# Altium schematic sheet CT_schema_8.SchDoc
size 287 x 160 mm
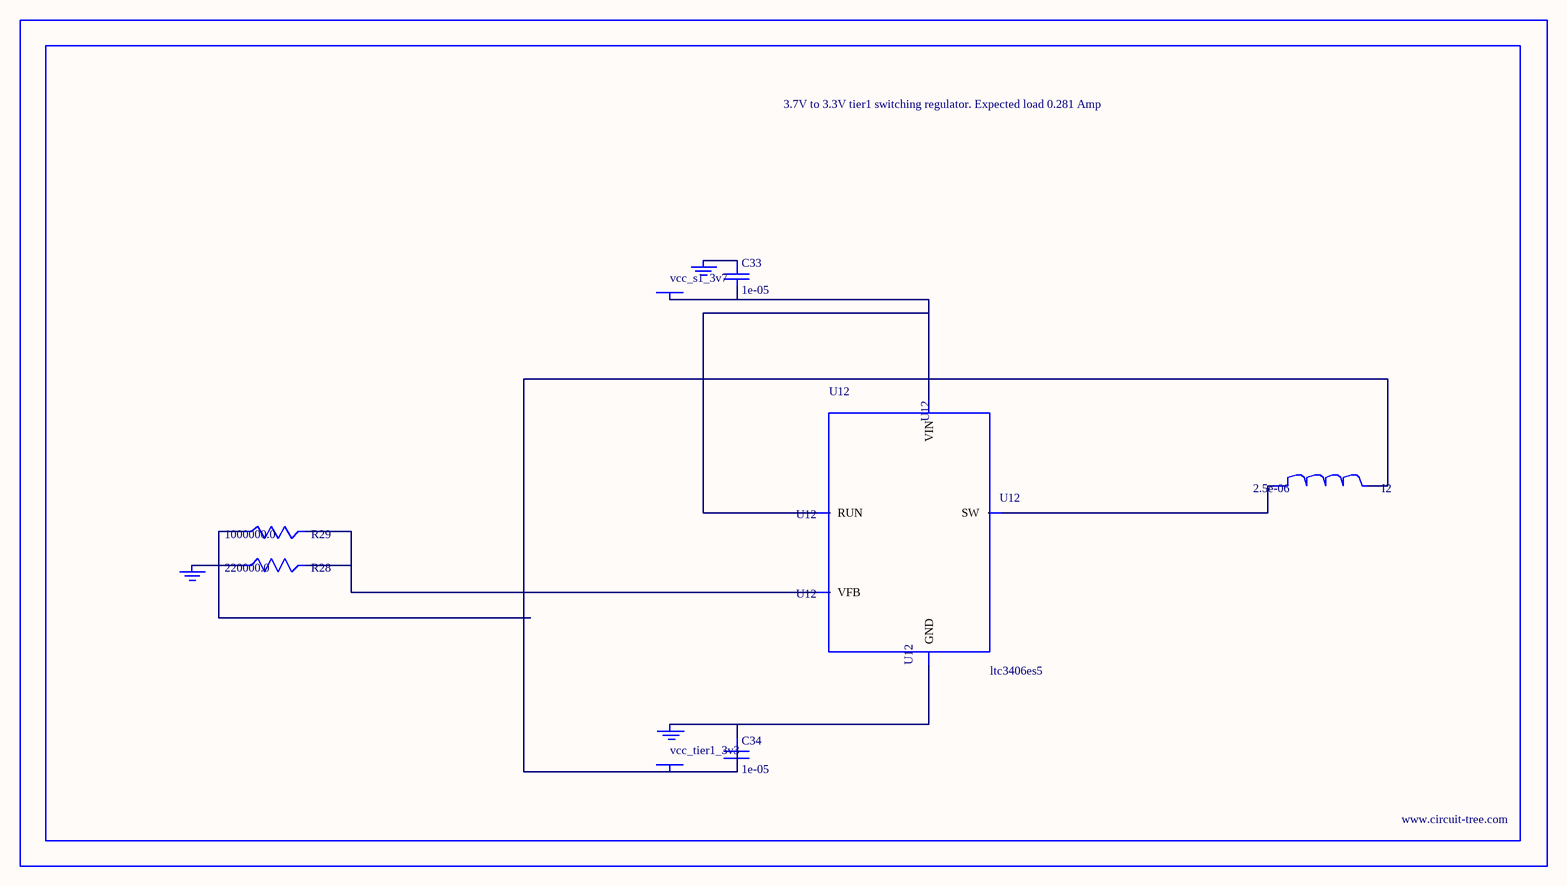
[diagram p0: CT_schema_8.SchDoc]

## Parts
BORDER7  (no value)
C33  1e-05  [C0805]
C34  1e-05  [C0805]
GND_INSTANCE_7_0  (no value)
GND_INSTANCE_7_1  (no value)
GND_INSTANCE_7_2  (no value)
I2  2.5e-06  [DR1040]
POWER_INSTANCE_7_0  vcc_tier1_3v3
POWER_INSTANCE_7_1  vcc_s1_3v7
R28  220000.0  [R0603]
R29  1000000.0  [R0603]
U12  ltc3406es5  [TSOT-23-5]

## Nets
NetC33_1: C33.1 GND_INSTANCE_7_1.0(GND)
NetC33_2: C33.2 POWER_INSTANCE_7_1.0(PWR) U12.1(RUN) U12.4(VIN)
NetC34_1: C34.1 GND_INSTANCE_7_0.0(GND) U12.2(GND)
NetC34_2: C34.2 I2.2 POWER_INSTANCE_7_0.0(PWR) R29.1
NetGND_INSTANCE_7_2_0: GND_INSTANCE_7_2.0(GND) R28.1
NetI2_1: I2.1 U12.3(SW)
NetR28_2: R28.2 R29.2 U12.5(VFB)

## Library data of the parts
BORDER7 = BORDER_PAGE7
C33 C34 = C0805C106K8RACTU
GND_INSTANCE_7_0-GND_INSTANCE_7_2 = GND
I2 = DR1040-2R5-R
POWER_INSTANCE_7_0 POWER_INSTANCE_7_1 = PWR
R28 = RC0603JR-07220KL
R29 = RC0603JR-071ML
